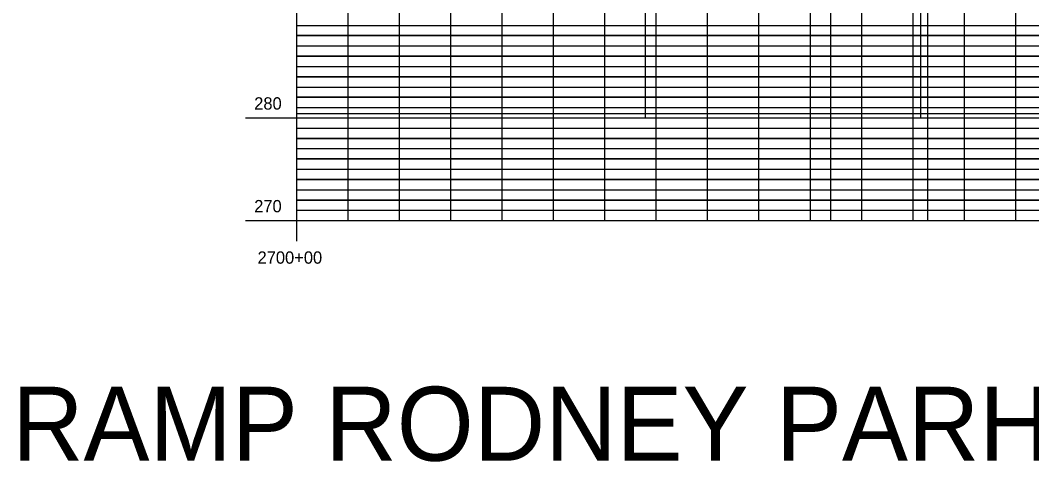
# Model space of a CAD drawing. Extents: x 1195880 to 1289360, y 2059330 to 2086925.
# Drawn here: x 1196929.3 to 1197421.6, y 2062106.9 to 2062321.8 of the extents above; entities that cross this region are included whole.
import ezdxf

# ---------------------------------------------------------------- set-up
doc = ezdxf.new("R2010")
doc.units = 0
for name, color, linetype in [('51', 7, 'Continuous'), ('Default', 7, 'Continuous'), ('Grid', 7, 'Continuous'), ('Grid Lables', 7, 'Continuous')]:
    doc.layers.add(name, color=color, linetype=linetype)

msp = doc.modelspace()

# ---------------------------------------------------------------- linework, layer by layer
at = {"layer": 'Default'}
for p, q in [((1197371.02, 2062224.28), (1197371.02, 2062868.37)), ((1197233.63, 2062274.28), (1197233.63, 2062593.89)), ((1197323.88, 2062224.28), (1197323.88, 2062571.74)), ((1197367.58, 2062274.28), (1197367.58, 2062558.8)), ((1197063.84, 2062224.28), (1197418.17, 2062224.28)), ((1197063.84, 2062224.28), (1197371.02, 2062224.28)), ((1197063.84, 2062224.28), (1197323.88, 2062224.28))]:
    msp.add_line(p, q, dxfattribs=at)
at = {"layer": 'Grid'}
for p, q in [((1197063.84, 2062224.28), (1197063.84, 2062824.28)), ((1197088.84, 2062224.28), (1197088.84, 2062824.28)), ((1197113.84, 2062224.28), (1197113.84, 2062824.28)), ((1197138.84, 2062224.28), (1197138.84, 2062824.28)), ((1197163.84, 2062224.28), (1197163.84, 2062824.28)), ((1197188.84, 2062224.28), (1197188.84, 2062824.28)), ((1197213.84, 2062224.28), (1197213.84, 2062824.28)), ((1197238.84, 2062224.28), (1197238.84, 2062824.28)), ((1197263.84, 2062224.28), (1197263.84, 2062824.28)), ((1197288.84, 2062224.28), (1197288.84, 2062824.28)), ((1197313.84, 2062224.28), (1197313.84, 2062824.28)), ((1197338.84, 2062224.28), (1197338.84, 2062824.28)), ((1197363.84, 2062224.28), (1197363.84, 2062824.28)), ((1197388.84, 2062224.28), (1197388.84, 2062824.28)), ((1197413.84, 2062224.28), (1197413.84, 2062824.28)), ((1197063.84, 2062319.28), (1197066.84, 2062319.28)), ((1197063.84, 2062319.28), (1197563.84, 2062319.28)), ((1197063.84, 2062314.28), (1197066.84, 2062314.28)), ((1197063.84, 2062314.28), (1197563.84, 2062314.28)), ((1197563.84, 2062314.28), (1197063.84, 2062314.28)), ((1197063.84, 2062309.28), (1197066.84, 2062309.28)), ((1197063.84, 2062309.28), (1197563.84, 2062309.28)), ((1197063.84, 2062304.28), (1197066.84, 2062304.28)), ((1197063.84, 2062304.28), (1197563.84, 2062304.28)), ((1197563.84, 2062304.28), (1197063.84, 2062304.28)), ((1197063.84, 2062299.28), (1197066.84, 2062299.28)), ((1197063.84, 2062299.28), (1197563.84, 2062299.28)), ((1197063.84, 2062294.28), (1197066.84, 2062294.28)), ((1197063.84, 2062294.28), (1197563.84, 2062294.28)), ((1197563.84, 2062294.28), (1197063.84, 2062294.28)), ((1197063.84, 2062289.28), (1197066.84, 2062289.28)), ((1197063.84, 2062289.28), (1197563.84, 2062289.28)), ((1197063.84, 2062284.28), (1197066.84, 2062284.28)), ((1197063.84, 2062284.28), (1197563.84, 2062284.28)), ((1197563.84, 2062284.28), (1197063.84, 2062284.28)), ((1197063.84, 2062279.28), (1197066.84, 2062279.28)), ((1197063.84, 2062279.28), (1197563.84, 2062279.28)), ((1197063.84, 2062276.46), (1197563.84, 2062276.46)), ((1197038.84, 2062274.28), (1197063.84, 2062274.28)), ((1197063.84, 2062274.28), (1197563.84, 2062274.28)), ((1197063.84, 2062269.28), (1197066.84, 2062269.28)), ((1197063.84, 2062269.28), (1197563.84, 2062269.28)), ((1197063.84, 2062264.28), (1197066.84, 2062264.28)), ((1197063.84, 2062264.28), (1197563.84, 2062264.28)), ((1197563.84, 2062264.28), (1197063.84, 2062264.28)), ((1197063.84, 2062259.28), (1197066.84, 2062259.28)), ((1197063.84, 2062259.28), (1197563.84, 2062259.28)), ((1197063.84, 2062254.28), (1197066.84, 2062254.28)), ((1197063.84, 2062254.28), (1197563.84, 2062254.28)), ((1197563.84, 2062254.28), (1197063.84, 2062254.28)), ((1197063.84, 2062249.28), (1197066.84, 2062249.28)), ((1197063.84, 2062249.28), (1197563.84, 2062249.28)), ((1197063.84, 2062244.28), (1197066.84, 2062244.28)), ((1197063.84, 2062244.28), (1197563.84, 2062244.28)), ((1197563.84, 2062244.28), (1197063.84, 2062244.28)), ((1197063.84, 2062239.28), (1197066.84, 2062239.28)), ((1197063.84, 2062239.28), (1197563.84, 2062239.28)), ((1197063.84, 2062234.28), (1197066.84, 2062234.28)), ((1197063.84, 2062234.28), (1197563.84, 2062234.28)), ((1197563.84, 2062234.28), (1197063.84, 2062234.28)), ((1197063.84, 2062229.28), (1197066.84, 2062229.28)), ((1197063.84, 2062229.28), (1197563.84, 2062229.28)), ((1197088.84, 2062224.28), (1197088.84, 2062227.28)), ((1197113.84, 2062224.28), (1197113.84, 2062227.28)), ((1197138.84, 2062224.28), (1197138.84, 2062227.28)), ((1197163.84, 2062224.28), (1197163.84, 2062227.28)), ((1197188.84, 2062224.28), (1197188.84, 2062227.28)), ((1197213.84, 2062224.28), (1197213.84, 2062227.28)), ((1197238.84, 2062224.28), (1197238.84, 2062227.28)), ((1197263.84, 2062224.28), (1197263.84, 2062227.28)), ((1197288.84, 2062224.28), (1197288.84, 2062227.28)), ((1197313.84, 2062224.28), (1197313.84, 2062227.28)), ((1197338.84, 2062224.28), (1197338.84, 2062227.28)), ((1197363.84, 2062224.28), (1197363.84, 2062227.28)), ((1197388.84, 2062224.28), (1197388.84, 2062227.28)), ((1197413.84, 2062224.28), (1197413.84, 2062227.28)), ((1197038.84, 2062224.28), (1197063.84, 2062224.28)), ((1197063.84, 2062224.28), (1197563.84, 2062224.28)), ((1197063.84, 2062214.28), (1197063.84, 2062224.28))]:
    msp.add_line(p, q, dxfattribs=at)

# ---------------------------------------------------------------- texts
at = {"layer": '51'}
msp.add_text('-', height=0.0001, rotation=360, dxfattribs=at).set_placement((1197063.84, 2062224.28))
at = {"layer": 'Default'}
msp.add_text('RAMP RODNEY PARHAM TO WB I-630', height=36, rotation=360, dxfattribs=at).set_placement((1196925.33, 2062107.39))
at = {"layer": 'Grid Lables'}
for s, p in [('280', (1197043.15, 2062278.28)), ('270', (1197043.15, 2062228.28)), ('2700+00', (1197044.78, 2062203.28))]:
    msp.add_text(s, height=6, rotation=360, dxfattribs=at).set_placement(p)

doc.saveas('drawing.dxf')
